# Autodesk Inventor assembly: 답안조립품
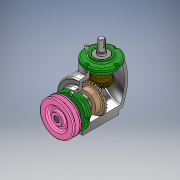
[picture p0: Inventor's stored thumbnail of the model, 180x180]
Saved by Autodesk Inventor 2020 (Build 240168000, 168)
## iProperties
Created: 2023-12
Part Number: 답안조립품
Document SubType Name: Weldment
Designer: 1강의실14
Weld Material: Welded Aluminum-6061
Author: 1강의실14
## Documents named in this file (15)
- C:\Users\1강의실14\Desktop\731203V1005\답안조립품.iam
- C:\Users\1강의실14\Desktop\731203V1005\본체.ipt
- C:\Users\1강의실14\Desktop\731203V1005\커버.ipt
- C:\Users\1강의실14\Desktop\731203V1005\베어링 6203.ipt
- C:\Users\1강의실14\Desktop\731203V1005\오일실 17 x 32 x 8.ipt
- C:\Users\1강의실14\Desktop\731203V1005\메인 축.ipt
- 메인 축.ipt
- C:\Users\1강의실14\Desktop\731203V1005\키 5 x 5 x 14.ipt
- C:\Users\1강의실14\Desktop\731203V1005\메인 베벨기어.ipt
- C:\Users\1강의실14\Desktop\731203V1005\서브 축.ipt
- 서브 축.ipt
- C:\Users\1강의실14\Desktop\731203V1005\키 4 x 4 x 14.ipt
- C:\Users\1강의실14\Desktop\731203V1005\서브 베벨기어.ipt
- C:\Users\1강의실14\Desktop\731203V1005\V-벨트풀리.ipt
- C:\Users\1강의실14\Desktop\731203V1005\볼트 M4 x 10.ipt
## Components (1 placed, 1 different names)
1. V-벨트풀리:1 — 플러쉬:1
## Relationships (1: Flush 1)
- 플러쉬:1 [Flush]: V-벨트풀리:1
